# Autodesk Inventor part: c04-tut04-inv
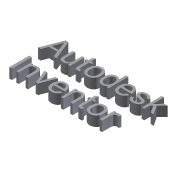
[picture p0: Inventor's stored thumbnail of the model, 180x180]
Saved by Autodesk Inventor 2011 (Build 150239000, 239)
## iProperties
Created: 2010-02
Part Number: c04-tut04-inv
Document SubType Name: Modeling
Designer: CADSoft
Density: 1 g/cm^3
Author: CADSoft
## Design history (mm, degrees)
sketch "Sketch1"
  geometry: L1 (-8.398, 18.152)-(22.665, 18.152); L2 (22.665, 18.152)-(22.665, 5.204); L3 (22.665, 5.204)-(-8.398, 5.204); L4 (-8.398, 5.204)-(-8.398, 18.152); 1 further point
  constraints: 2 other
extrude "Extrusion1" new body sketch "Sketch1" distance "d0" = 2.5; taper "d1" = 0 deg
body "Solid1"
